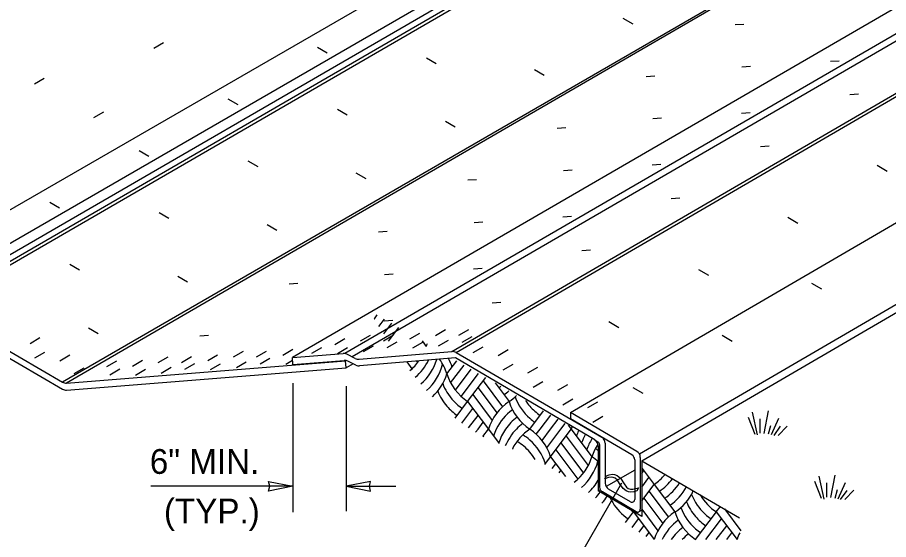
# Model space of a CAD drawing. Extents: x 99862 to 103151, y 100000 to 102076.
# Drawn here: x 101674 to 102236, y 100697 to 101034 of the extents above; entities that cross this region are included whole.
import ezdxf

# ---------------------------------------------------------------- set-up
doc = ezdxf.new("R2010")
doc.units = 0
for name, color, linetype in [('Level 15', 7, 'Continuous'), ('Level 20', 7, 'Continuous'), ('Level 3', 7, 'Continuous'), ('Level 31', 7, 'Continuous'), ('Level 33', 7, 'Continuous'), ('Level 34', 7, 'Continuous'), ('Level 36', 7, 'Continuous')]:
    doc.layers.add(name, color=color, linetype=linetype)

msp = doc.modelspace()

# ---------------------------------------------------------------- linework, layer by layer
at = {"layer": 'Level 15'}
for p, q in [((101851.92, 100798.26), (101851.92, 100714.91)), ((101886.21, 100796.21), (101886.21, 100715.69)), ((102054.08, 100738.39), (102055.91, 100739.16)), ((102055.91, 100739.16), (102057.68, 100739.45)), ((102057.68, 100739.45), (102059.37, 100739.25)), ((102059.37, 100739.25), (102061, 100738.57)), ((102063.87, 100733.63), (102021.78, 100660.73)), ((102053.02, 100736.56), (102054.08, 100738.39)), ((102055.33, 100737.3), (102053.02, 100736.56)), ((102057.04, 100737.57), (102055.33, 100737.3)), ((102058.4, 100737.42), (102057.04, 100737.57)), ((102059.63, 100736.92), (102058.4, 100737.42)), ((102061.09, 100735.67), (102059.63, 100736.92)), ((102061, 100738.57), (102063.08, 100736.83)), ((102062.55, 100733.58), (102061.09, 100735.67)), ((102064.82, 100730.18), (102062.55, 100733.58)), ((102063.08, 100736.83), (102065.6, 100733.2)), ((101851.92, 100731.69), (101760.16, 100731.69)), ((101886.21, 100731.69), (101918.21, 100731.69)), ((102066.75, 100728.64), (102064.82, 100730.18)), ((102065.6, 100733.2), (102066.99, 100731.21)), ((102068.28, 100727.99), (102066.75, 100728.64)), ((102066.99, 100731.21), (102068.15, 100730.26)), ((102068.15, 100730.26), (102069.49, 100729.79)), ((102069.88, 100727.81), (102068.28, 100727.99)), ((102069.49, 100729.79), (102071.13, 100729.73)), ((102071.64, 100728.08), (102069.88, 100727.81)), ((102071.13, 100729.73), (102074.71, 100730.66)), ((102073.66, 100728.83), (102071.64, 100728.08)), ((102074.71, 100730.66), (102073.66, 100728.83))]:
    msp.add_line(p, q, dxfattribs=at)
for points in [[(101851.92, 100731.69), (101836.2, 100728.6), (101836.92, 100731.69), (101836.2, 100734.77)], [(101886.21, 100731.69), (101901.94, 100728.6), (101901.21, 100731.69), (101901.94, 100734.77)]]:
    msp.add_lwpolyline(points, close=True, dxfattribs=at)
at = {"layer": 'Level 3'}
for p, q in [((101904.42, 100839.82), (101906.25, 100842.27)), ((101904.35, 100839.73), (101904.42, 100839.82)), ((101907.38, 100834.86), (101910.92, 100839.57)), ((101910.46, 100830.06), (101915.58, 100836.88)), ((101913.6, 100825.34), (101920.24, 100834.19)), ((101935.14, 100825.59), (101937.83, 100822)), ((101931.62, 100812.46), (101932.32, 100811.52)), ((101951.19, 100804.18), (101957.55, 100812.65)), ((101925.33, 100811.93), (101928.65, 100807.51)), ((101953.6, 100798.48), (101962.21, 100809.96)), ((101956.7, 100793.7), (101966.87, 100807.27)), ((101960.37, 100789.69), (101971.53, 100804.58)), ((101964.56, 100786.36), (101976.2, 100801.88)), ((101971.24, 100795.27), (101983.43, 100779.02)), ((101974.58, 100799.73), (101987.1, 100783.04)), ((101982.28, 100798.37), (101991.29, 100786.36)), ((101967.9, 100790.82), (101980.33, 100774.24)), ((101956.6, 100775.75), (101964.56, 100786.36)), ((101964.56, 100786.36), (101977.92, 100768.54)), ((101960.82, 100772.47), (101967.9, 100781.91)), ((102004.65, 100768.54), (102013.5, 100780.35)), ((101965.18, 100769.38), (101971.24, 100777.45)), ((101971.24, 100768.54), (101974.58, 100773)), ((102011.33, 100768.54), (102018.16, 100777.65)), ((102018.01, 100768.54), (102022.83, 100774.96)), ((101969.71, 100766.51), (101971.24, 100768.54)), ((101974.43, 100763.88), (101977.92, 100768.54)), ((101977.92, 100768.54), (101984.86, 100759.3)), ((102008.84, 100765.22), (102011.33, 100768.54)), ((102012.51, 100761.2), (102018.01, 100768.54)), ((102015.61, 100756.43), (102024.7, 100768.54)), ((102018.01, 100750.73), (102031.38, 100768.54)), ((102024.7, 100768.54), (102027.49, 100772.27)), ((102029.42, 100771.16), (102031.38, 100768.54)), ((102031.38, 100768.54), (102044.74, 100750.73)), ((101974.58, 100764.09), (101974.93, 100763.62)), ((102028.04, 100764.09), (102042.34, 100745.02)), ((102024.7, 100759.63), (102039.24, 100740.25)), ((102014.3, 100745.78), (102018.01, 100750.73)), ((102018.01, 100750.73), (102027.56, 100737.99)), ((102021.36, 100755.18), (102035.57, 100736.23)), ((102019.02, 100743.15), (102021.36, 100746.27)), ((102023.64, 100740.41), (102024.7, 100741.82)), ((102076.81, 100740.03), (102078.15, 100741.82)), ((102077.07, 100743.26), (102084.84, 100732.91)), ((102076.81, 100731.12), (102081.49, 100737.36)), ((102076.81, 100722.21), (102084.84, 100732.91)), ((102081.49, 100728.45), (102089.91, 100717.23)), ((102084.84, 100732.91), (102098.2, 100715.09)), ((102078.15, 100724), (102090.34, 100707.75)), ((102076.81, 100716.88), (102087.24, 100702.97)), ((102089.8, 100717.37), (102094.01, 100711.76)), ((102124.93, 100715.09), (102127.54, 100718.56)), ((102130.14, 100717.05), (102140.7, 100702.97)), ((102066.4, 100708.33), (102071.47, 100715.09)), ((102071.47, 100715.09), (102084.84, 100697.27)), ((102111.56, 100697.27), (102124.94, 100715.1)), ((102124.93, 100715.09), (102138.29, 100697.27)), ((102070.69, 100705.13), (102074.81, 100710.63)), ((102075.08, 100702.08), (102078.15, 100706.18)), ((102118.25, 100697.27), (102128.27, 100710.63)), ((102124.93, 100697.27), (102131.61, 100706.18)), ((102079.59, 100699.18), (102081.49, 100701.72)), ((102131.61, 100697.27), (102134.95, 100701.72))]:
    msp.add_line(p, q, dxfattribs=at)
for centre, start, end in [((101970.06, 100811.75), 159.3169, 162.3566), ((101905.6, 100832.25), 309.9841, 324.4388), ((101908.94, 100827.8), 310.3125, 334.2574), ((101912.28, 100823.34), 310.8361, 343.1622), ((101918.96, 100793.93), 17.6434, 35.7536), ((101922.31, 100798.39), 17.6434, 27.8328), ((101915.62, 100818.89), 311.5453, 345.7713), ((101918.96, 100814.43), 312.5228, 342.3566), ((101983.42, 100814.43), 197.6435, 236.0964), ((101980.08, 100809.98), 200.8778, 211.332), ((101965.74, 100823.34), 303.9036, 306.7417), ((101976.74, 100805.52), 201.4344, 220.9416), ((101980.08, 100809.98), 211.3319, 236.0964), ((101969.08, 100818.89), 303.9036, 310.7192), ((101972.42, 100814.43), 303.9036, 314.6022), ((102010.15, 100758.29), 123.9036, 162.3566), ((102023.51, 100796.61), 197.6434, 236.0964), ((102026.86, 100801.07), 200.2432, 228.9599), ((102030.2, 100805.52), 213.0676, 220.9416), ((101976.74, 100805.52), 220.9415, 236.0964), ((102013.49, 100753.84), 126.3063, 154.2266), ((102030.2, 100805.52), 220.9415, 236.0964), ((102016.83, 100749.38), 127.1006, 145.4911), ((102026.86, 100801.07), 228.9599, 236.0964), ((102013.49, 100753.84), 154.2265, 162.3566), ((102016.83, 100749.38), 145.491, 162.3566), ((102020.17, 100744.93), 135.7127, 157.8023), ((102023.51, 100740.47), 123.9036, 152.9039), ((102020.17, 100744.93), 126.331, 135.7128), ((101985.79, 100740.47), 17.6434, 56.0963), ((102063.61, 100758.29), 160.1417, 162.3566), ((102066.95, 100753.84), 156.3962, 162.3566), ((101982.44, 100736.02), 48.9597, 58.5465), ((101982.44, 100736.02), 17.6434, 48.9597), ((102070.29, 100749.38), 152.6781, 162.3566), ((102073.63, 100744.93), 148.9713, 162.3566), ((101975.76, 100727.11), 57.6047, 58.4874), ((101979.1, 100731.57), 40.9413, 59.3021), ((102076.97, 100740.47), 147.0551, 162.3566), ((102029.22, 100727.11), 54.7281, 58.4874), ((101979.1, 100731.57), 31.1036, 40.9414), ((102012.51, 100760.98), 307.7999, 342.3566), ((102025.88, 100722.66), 47.4488, 56.0964), ((102015.86, 100756.52), 310.97, 345.0113), ((102065.97, 100760.98), 303.9036, 320.1124), ((102019.2, 100752.07), 313.6475, 330.9069), ((102069.31, 100756.52), 303.9036, 323.8243), ((102072.64, 100752), 303.9036, 327.6171), ((102022.54, 100747.61), 316.2152, 324.341), ((102076.07, 100747.53), 303.9036, 331.2534), ((102079.4, 100742.98), 303.9036, 335.0799), ((102025.88, 100743.16), 318.426, 327.9747), ((102087, 100738.7), 205.6332, 211.332), ((102140.45, 100738.7), 201.1851, 211.332), ((102143.78, 100743.18), 210.3391, 236.1414), ((102087, 100738.7), 211.3319, 236.0964), ((102133.77, 100729.79), 200.557, 228.9599), ((102137.11, 100734.25), 201.7429, 220.9416), ((102140.45, 100738.7), 211.3319, 236.0964), ((102090.34, 100743.16), 233.2892, 236.0964), ((102117.06, 100687.02), 123.9036, 162.3566), ((102130.43, 100725.34), 197.6434, 236.0964), ((102137.11, 100734.25), 220.9415, 236.0964), ((102120.41, 100682.56), 126.3063, 154.2266), ((102123.75, 100678.11), 127.1006, 145.4911), ((102127.09, 100673.65), 126.331, 135.7128), ((102133.77, 100729.79), 228.9599, 236.0964), ((102170.52, 100687.02), 154.3046, 162.3566)]:
    msp.add_arc(centre, 33.82, start, end, dxfattribs=at)
at = {"layer": 'Level 31'}
for p, q in [((102151.5, 100764.84), (102148.21, 100779.53)), ((102155.83, 100765.79), (102158.56, 100780.28)), ((102149.9, 100765.13), (102145.57, 100776.14)), ((102153.2, 100766.07), (102153.2, 100775.29)), ((102160.54, 100765.03), (102165.34, 100775.58)), ((102158.56, 100765.5), (102160.17, 100770.96)), ((102162.14, 100764.47), (102166.28, 100770.4)), ((102164.78, 100764.47), (102170.71, 100770.49)), ((102048.75, 100757.68), (102048.75, 100728.64)), ((102076.81, 100748.08), (102076.81, 100712.1)), ((102192.85, 100723.7), (102188.52, 100734.72)), ((102194.45, 100723.42), (102191.16, 100738.11)), ((102196.15, 100724.64), (102196.15, 100733.87)), ((102198.78, 100724.36), (102201.51, 100738.86)), ((102203.49, 100723.61), (102208.29, 100734.15)), ((102076.81, 100712.1), (102048.75, 100728.64)), ((102201.51, 100724.08), (102203.11, 100729.54)), ((102205.09, 100723.04), (102209.23, 100728.97)), ((102207.73, 100723.04), (102213.66, 100729.07))]:
    msp.add_line(p, q, dxfattribs=at)
for points in [[(102076.81, 100748.08), (102988.41, 101279.88)], [(102076.81, 100748.08), (102139.93, 100711.36)], [(102050.12, 100729.43), (102048.75, 100728.64)]]:
    msp.add_lwpolyline(points, dxfattribs=at)
msp.add_arc((102044.25, 100757.68), 4.5, 0, 59.4535, dxfattribs=at)
at = {"layer": 'Level 33'}
for p, q in [((101954.47, 100818.63), (102870.96, 101352.22)), ((101957.1, 100818.04), (102873.59, 101351.62)), ((102799.37, 101348.12), (101885.46, 100817.33)), ((102804.53, 101346.29), (101890.1, 100815.2)), ((102758.7, 101342.08), (101851.56, 100814.75)), ((101851.56, 100814.75), (101884.24, 100817.4)), ((101851.92, 100810.26), (101851.56, 100814.75)), ((101851.92, 100810.26), (101884.87, 100812.94)), ((101892.13, 100814.18), (101886.62, 100816.94)), ((101892.48, 100809.85), (101887.25, 100812.47)), ((102073.7, 100754.2), (102030.95, 100779.41)), ((102030.95, 100779.41), (102030.95, 100775.23)), ((102070.54, 100751.89), (102030.95, 100775.23)), ((102046.54, 100761.56), (102048.76, 100760.24)), ((102049.65, 100758.69), (102049.65, 100731.21)), ((102053.25, 100759.51), (102053.25, 100733.78)), ((102075.91, 100750.33), (102075.91, 100716.82)), ((102072.31, 100748.79), (102072.31, 100723.13)), ((102073.2, 100715.27), (102051.42, 100728.11)), ((102069.6, 100721.58), (102055.46, 100729.91))]:
    msp.add_line(p, q, dxfattribs=at)
for points in [[(102030.95, 100779.41), (102943.44, 101311.74)], [(102075.32, 100752.56), (102987.82, 101284.89)], [(101894.51, 100813.72), (101954.47, 100818.63)], [(101957.1, 100818.04), (102051.01, 100763.4)], [(101956.73, 100814.55), (101894.87, 100809.39)], [(102046.54, 100761.56), (101956.73, 100814.55)], [(102072.33, 100742.1), (102053.84, 100731.55)], [(102076.81, 100716.29), (102075.01, 100715.26)]]:
    msp.add_lwpolyline(points, dxfattribs=at)
for centre, radius, start, end in [((101954.83, 100814.15), 4.5, 59.809, 94.6841), ((101884.61, 100812.91), 4.5, 63.4087, 94.6412), ((101885.23, 100808.45), 4.5, 63.4087, 94.6412), ((101894.14, 100818.21), 4.5, 243.4087, 274.6841), ((101894.5, 100813.88), 4.5, 243.4087, 274.7691), ((102048.75, 100759.51), 4.5, 0, 59.809), ((102047.85, 100758.69), 1.8, 0, 59.4535), ((102068.71, 100748.79), 3.6, 0, 59.4804), ((102071.41, 100750.33), 4.5, 0, 59.4804), ((102057.75, 100733.78), 4.5, 180, 239.4804), ((102053.25, 100731.21), 3.6, 180, 239.4804), ((102070.51, 100723.13), 1.8, 239.4804, 0), ((102074.11, 100716.82), 1.8, 239.4804, 0)]:
    msp.add_arc(centre, radius, start, end, dxfattribs=at)
at = {"layer": 'Level 34'}
for p, q in [((102069.69, 101141.37), (101595.22, 100867.16)), ((102087.81, 101130.9), (101614.01, 100856.17)), ((102092.4, 101126.39), (101618.65, 100851.66)), ((102094.82, 101123.51), (101620.99, 100848.7)), ((102096.63, 101122.16), (101622.29, 100847.06)), ((102179.2, 101074.44), (101703.3, 100798.93)), ((102180.8, 101074.01), (101705.93, 100798.33)), ((101623.42, 100841.04), (101703.32, 100794.41)), ((101624.29, 100845.03), (101703.3, 100798.93)), ((101705.93, 100798.33), (101885.85, 100812.7)), ((101886.13, 100812.86), (101885.85, 100812.7)), ((101886.21, 100808.21), (101885.85, 100812.7)), ((101705.95, 100793.82), (101886.21, 100808.21)), ((101890.63, 100810.78), (101886.21, 100808.21))]:
    msp.add_line(p, q, dxfattribs=at)
for centre in [(101705.57, 100802.81), (101705.59, 100798.3)]:
    msp.add_arc(centre, 4.5, 239.7377, 274.6412, dxfattribs=at)
at = {"layer": 'Level 36'}
for p, q in [((102071.31, 101029.99), (102064.94, 101033.68)), ((102137.09, 101029.66), (102142.68, 101030.02)), ((101768.47, 101017.84), (101762.17, 101014.2)), ((101874.01, 101011.2), (101867.64, 101014.9)), ((101944.32, 101004.42), (101937.95, 101008.07)), ((102198.58, 101006.01), (102204.18, 101006.38)), ((102013.98, 100996.75), (102007.61, 101000.45)), ((102141.43, 101002.5), (102147.03, 101002.88)), ((101691.55, 100994.94), (101685.25, 100991.3)), ((102079.71, 100996.27), (102085.3, 100996.64)), ((101816.55, 100977.88), (101810.17, 100981.59)), ((102210.98, 100984.63), (102216.58, 100984.99)), ((101729.69, 100973.09), (101723.39, 100969.45)), ((101886.93, 100971.15), (101880.55, 100974.8)), ((102083.92, 100969.04), (102089.51, 100969.42)), ((102141.13, 100972.59), (102146.73, 100972.96)), ((101956.59, 100963.48), (101950.21, 100967.17)), ((102022.26, 100962.85), (102027.85, 100963.22)), ((101759.02, 100944.53), (101752.64, 100948.24)), ((102153.45, 100951.07), (102159.04, 100951.43)), ((101829.46, 100937.83), (101823.09, 100941.49)), ((102026.34, 100935.54), (102031.93, 100935.92)), ((102083.62, 100939.13), (102089.22, 100939.5)), ((102228.7, 100938.92), (102235.14, 100935.18)), ((101899.13, 100930.16), (101892.75, 100933.86)), ((101964.75, 100929.39), (101970.34, 100929.76)), ((101701.42, 100911.14), (101695.05, 100914.85)), ((102095.84, 100917.47), (102101.44, 100917.84)), ((101771.94, 100904.48), (101765.56, 100908.14)), ((101968.69, 100902.01), (101974.29, 100902.38)), ((102026.04, 100905.64), (102031.64, 100906.01)), ((102171.1, 100905.32), (102177.54, 100901.59)), ((101841.6, 100896.8), (101835.22, 100900.51)), ((101907.17, 100895.9), (101912.76, 100896.26)), ((102038.17, 100883.84), (102043.77, 100884.2)), ((101714.34, 100871.1), (101707.97, 100874.75)), ((101910.98, 100868.43), (101916.58, 100868.81)), ((101968.4, 100872.1), (101973.99, 100872.47)), ((102113.43, 100871.68), (102119.87, 100867.95)), ((101784, 100863.41), (101777.63, 100867.12)), ((101849.52, 100862.36), (101855.11, 100862.72)), ((102186.4, 100862.8), (102192.84, 100859.07)), ((101980.44, 100850.16), (101986.03, 100850.53)), ((101910.69, 100838.53), (101916.28, 100838.89)), ((102055.7, 100838.01), (102062.13, 100834.27)), ((101726.34, 100829.98), (101719.97, 100833.7)), ((101791.81, 100828.78), (101797.4, 100829.15)), ((101895.45, 100825.58), (101901.86, 100829.31)), ((101910.38, 100825.6), (101916.8, 100829.33)), ((101927.3, 100826.79), (101933.71, 100830.52)), ((101943.9, 100829.11), (101950.31, 100832.83)), ((101958.83, 100829.13), (101965.25, 100832.86)), ((102128.73, 100829.17), (102135.17, 100825.43)), ((101682.37, 100823.88), (101688.78, 100827.61)), ((101878.85, 100823.26), (101885.27, 100826.99)), ((101912.59, 100821.16), (101919.01, 100824.89)), ((101929.18, 100820.97), (101935.6, 100824.69)), ((101945.78, 100822.23), (101952.2, 100825.96)), ((101961.04, 100824.69), (101967.46, 100828.41)), ((101685.53, 100814.57), (101691.94, 100818.3)), ((101813.53, 100815.14), (101819.95, 100818.87)), ((101828.47, 100815.17), (101834.88, 100818.89)), ((101845.39, 100816.35), (101851.8, 100820.08)), ((101864.14, 100817.63), (101870.56, 100821.36)), ((101880.73, 100817.44), (101887.15, 100821.17)), ((101897.33, 100818.71), (101903.75, 100822.43)), ((101968.12, 100818.01), (101974.54, 100821.75)), ((101984.19, 100816.14), (101990.61, 100819.88)), ((101701.52, 100812.71), (101707.93, 100816.44)), ((101731.9, 100808.89), (101738.32, 100812.61)), ((101748.49, 100809.3), (101754.9, 100813.02)), ((101765.08, 100811.61), (101771.5, 100815.34)), ((101780.02, 100811.64), (101786.43, 100815.37)), ((101796.94, 100812.82), (101803.35, 100816.55)), ((101830.68, 100810.72), (101837.09, 100814.45)), ((101847.27, 100810.53), (101851.69, 100813.1)), ((101710.78, 100804.47), (101717.2, 100808.2)), ((101733.78, 100803.67), (101740.19, 100807.39)), ((101750.37, 100803.47), (101756.78, 100807.2)), ((101766.97, 100804.74), (101773.38, 100808.47)), ((101782.23, 100807.19), (101788.65, 100810.92)), ((101798.82, 100807), (101805.23, 100810.73)), ((101815.42, 100808.27), (101821.83, 100812)), ((101987.41, 100806.79), (101993.84, 100810.53)), ((102003.48, 100804.91), (102009.91, 100808.66)), ((102006.71, 100795.56), (102013.13, 100799.3)), ((102022.79, 100793.69), (102029.21, 100797.43)), ((102071, 100795.5), (102077.43, 100791.76)), ((102026.02, 100784.33), (102032.44, 100788.07)), ((102042.09, 100782.46), (102048.52, 100786.2)), ((102045.33, 100773.09), (102051.75, 100776.84))]:
    msp.add_line(p, q, dxfattribs=at)

# ---------------------------------------------------------------- texts
at = {"layer": 'Level 20'}
for s, p in [('6" MIN.', (101759.61, 100739.69)), ('(TYP.)', (101768.7, 100707.69))]:
    msp.add_text(s, height=16, dxfattribs=at).set_placement(p)

doc.saveas('drawing.dxf')
